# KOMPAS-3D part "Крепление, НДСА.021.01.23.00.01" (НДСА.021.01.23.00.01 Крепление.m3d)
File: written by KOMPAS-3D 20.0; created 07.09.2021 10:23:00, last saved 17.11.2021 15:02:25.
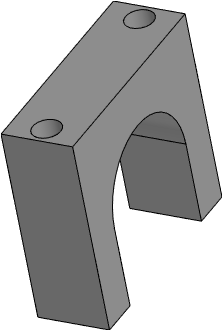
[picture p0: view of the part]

Document properties: Полное имя файла: C:\Users\s.pischagina\Desktop\PLM\НДСА.021.01.23.00.01 Крепление.m3d

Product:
- Part/product: Крепление  | designation НДСА.021.01.23.00.01
    Материал: АМг6  ГОСТ 4784-2019 (density 2640 kg/m3)
    Масса: 0.0270278
    additional columns: <item xmlns="http://appius.ru/pdm" xmlns:xs="http://www.w3.org/2001/XMLSchema" x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; <item xmlns="http://appius.ru/pdm" xmlns:xs="http://www.w3.org/2001/XMLSchema" x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; <item xmlns="http://appius.ru/pdm" xmlns:xs="http://www.w3.org/2001/XMLSchema" x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; <item xmlns="http://appius.ru/pdm" xmlns:xs="http://www.w3.org/2001/XMLSchema" x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; <item xmlns="http://appius.ru/pdm" xmlns:xs="http://www.w3.org/2001/XMLSchema" x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; <item xmlns="http://appius.ru/pdm" xmlns:xs="http://www.w3.org/2001/XMLSchema" x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
    source file: НДСА.021.01.23.00.01 Крепление.cdw

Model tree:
1. Эскиз:1
2. Элемент выдавливания:1
     Расстояние 1 = 14
3. Отверстие:1  (with: Элемент выдавливания:1)
     Глубина выреза = 38; Диаметр отверстия = 5.5; Угол конуса дна = 118; Расстояние 1 = 7; Расстояние 2 = 3.5
4. M5  (labels: cil0_24705-2004 coarse)
     Длина резьбы = 30; Шаг резьбы = 0.8; Номинальный диаметр резьбы = 5
5. Отверстие:2  (with: Элемент выдавливания:1, M5)  (labels: cil0_24705-2004 coarse; АМг6  ГОСТ 4784-2019)
     Глубина выреза = 38; Диаметр отверстия = 5.5; Угол конуса дна = 118; Расстояние 1 = 7; Расстояние 2 = -3.5; Длина резьбы = 30; Шаг резьбы = 0.8; Номинальный диаметр резьбы = 5

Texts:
  НДСА.021.01.23.00.01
